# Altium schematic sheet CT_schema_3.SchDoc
size 313 x 185 mm
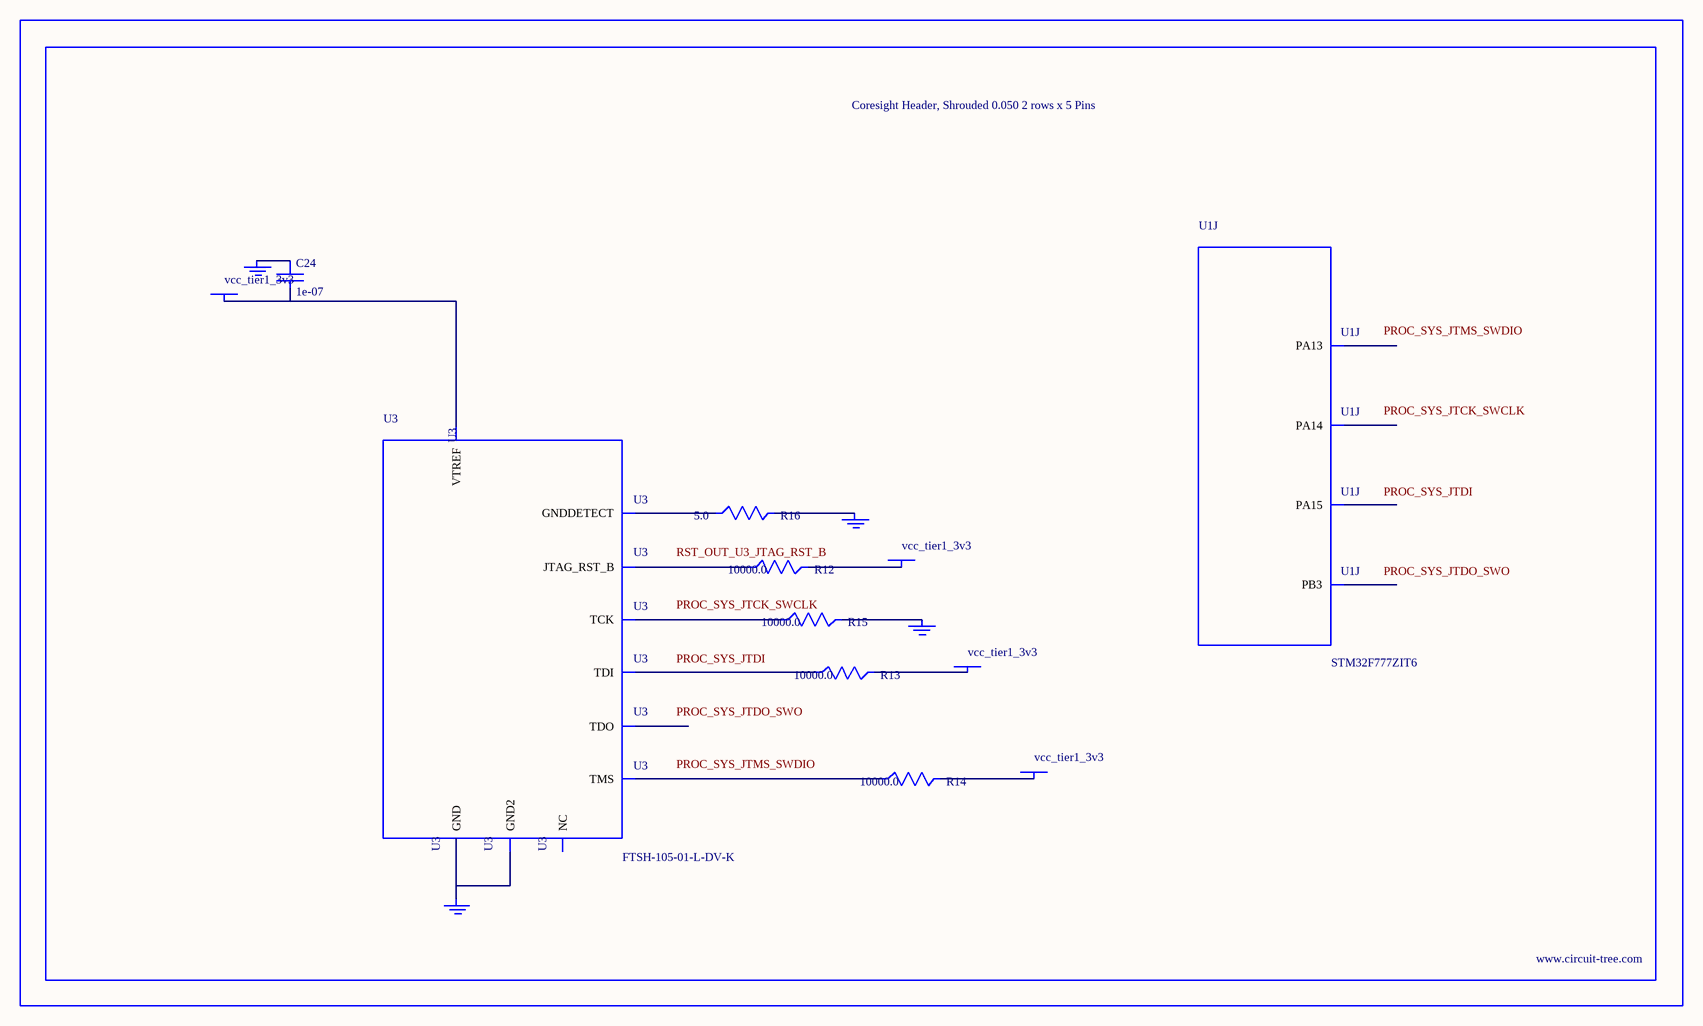
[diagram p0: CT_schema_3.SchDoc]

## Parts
BORDER2  (no value)
C24  1e-07  [C0402]
GND_INSTANCE_2_0  (no value)
GND_INSTANCE_2_1  (no value)
GND_INSTANCE_2_2  (no value)
GND_INSTANCE_2_3  (no value)
POWER_INSTANCE_2_0  vcc_tier1_3v3
POWER_INSTANCE_2_1  vcc_tier1_3v3
POWER_INSTANCE_2_2  vcc_tier1_3v3
POWER_INSTANCE_2_3  vcc_tier1_3v3
R12  10000.0  [R0603]
R13  10000.0  [R0603]
R14  10000.0  [R0603]
R15  10000.0  [R0603]
R16  5.0  [R0603]
U1  STM32F777ZIT6  [LQFP144]  (part J of 13)
U3  FTSH-105-01-L-DV-K  [SAMTEC_FTSH-105-01-L-DV-K]

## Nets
NetC24_1: C24.1 GND_INSTANCE_2_0.0(GND)
NetC24_2: C24.2 POWER_INSTANCE_2_0.0(PWR) U3.1(VTREF)
NetGND_INSTANCE_2_1_0: GND_INSTANCE_2_1.0(GND) R15.2
NetGND_INSTANCE_2_2_0: GND_INSTANCE_2_2.0(GND) R16.2
NetGND_INSTANCE_2_3_0: GND_INSTANCE_2_3.0(GND) U3.3(GND) U3.5(GND2)
NetPOWER_INSTANCE_2_1_0: POWER_INSTANCE_2_1.0(PWR) R14.2
NetPOWER_INSTANCE_2_2_0: POWER_INSTANCE_2_2.0(PWR) R13.2
NetPOWER_INSTANCE_2_3_0: POWER_INSTANCE_2_3.0(PWR) R12.2
NetR12_1: R12.1 U3.10(JTAG_RST_B)
NetR13_1: R13.1 U3.8(TDI)
NetR14_1: R14.1 U3.2(TMS)
NetR15_1: R15.1 U3.4(TCK)
NetR16_1: R16.1 U3.9(GNDDETECT)

Not connected (* = marked no-connect by the designer): U1 105(PA13) 109(PA14) 110(PA15) 133(PB3); U3 6(TDO) 7(NC)

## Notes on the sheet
- Labels drawn without touching a wire or pin: PROC_SYS_JTCK_SWCLK, PROC_SYS_JTDI, PROC_SYS_JTDO_SWO, PROC_SYS_JTMS_SWDIO, RST_OUT_U3_JTAG_RST_B

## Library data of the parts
BORDER2 = BORDER_PAGE2
C24 = C0402C104K3RACTU
GND_INSTANCE_2_0-GND_INSTANCE_2_3 = GND
POWER_INSTANCE_2_0-POWER_INSTANCE_2_3 = PWR
R12-R15 = RC0603JR-0710KL
R16 = ERJ-3GEYJ5R1V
